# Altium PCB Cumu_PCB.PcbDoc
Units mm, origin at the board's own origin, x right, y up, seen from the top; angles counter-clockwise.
Board outline 80 x 100 mm, 2 copper layers (Top Layer, Bottom Layer); 158 components, 124 nets, 568 pads, 298 vias.
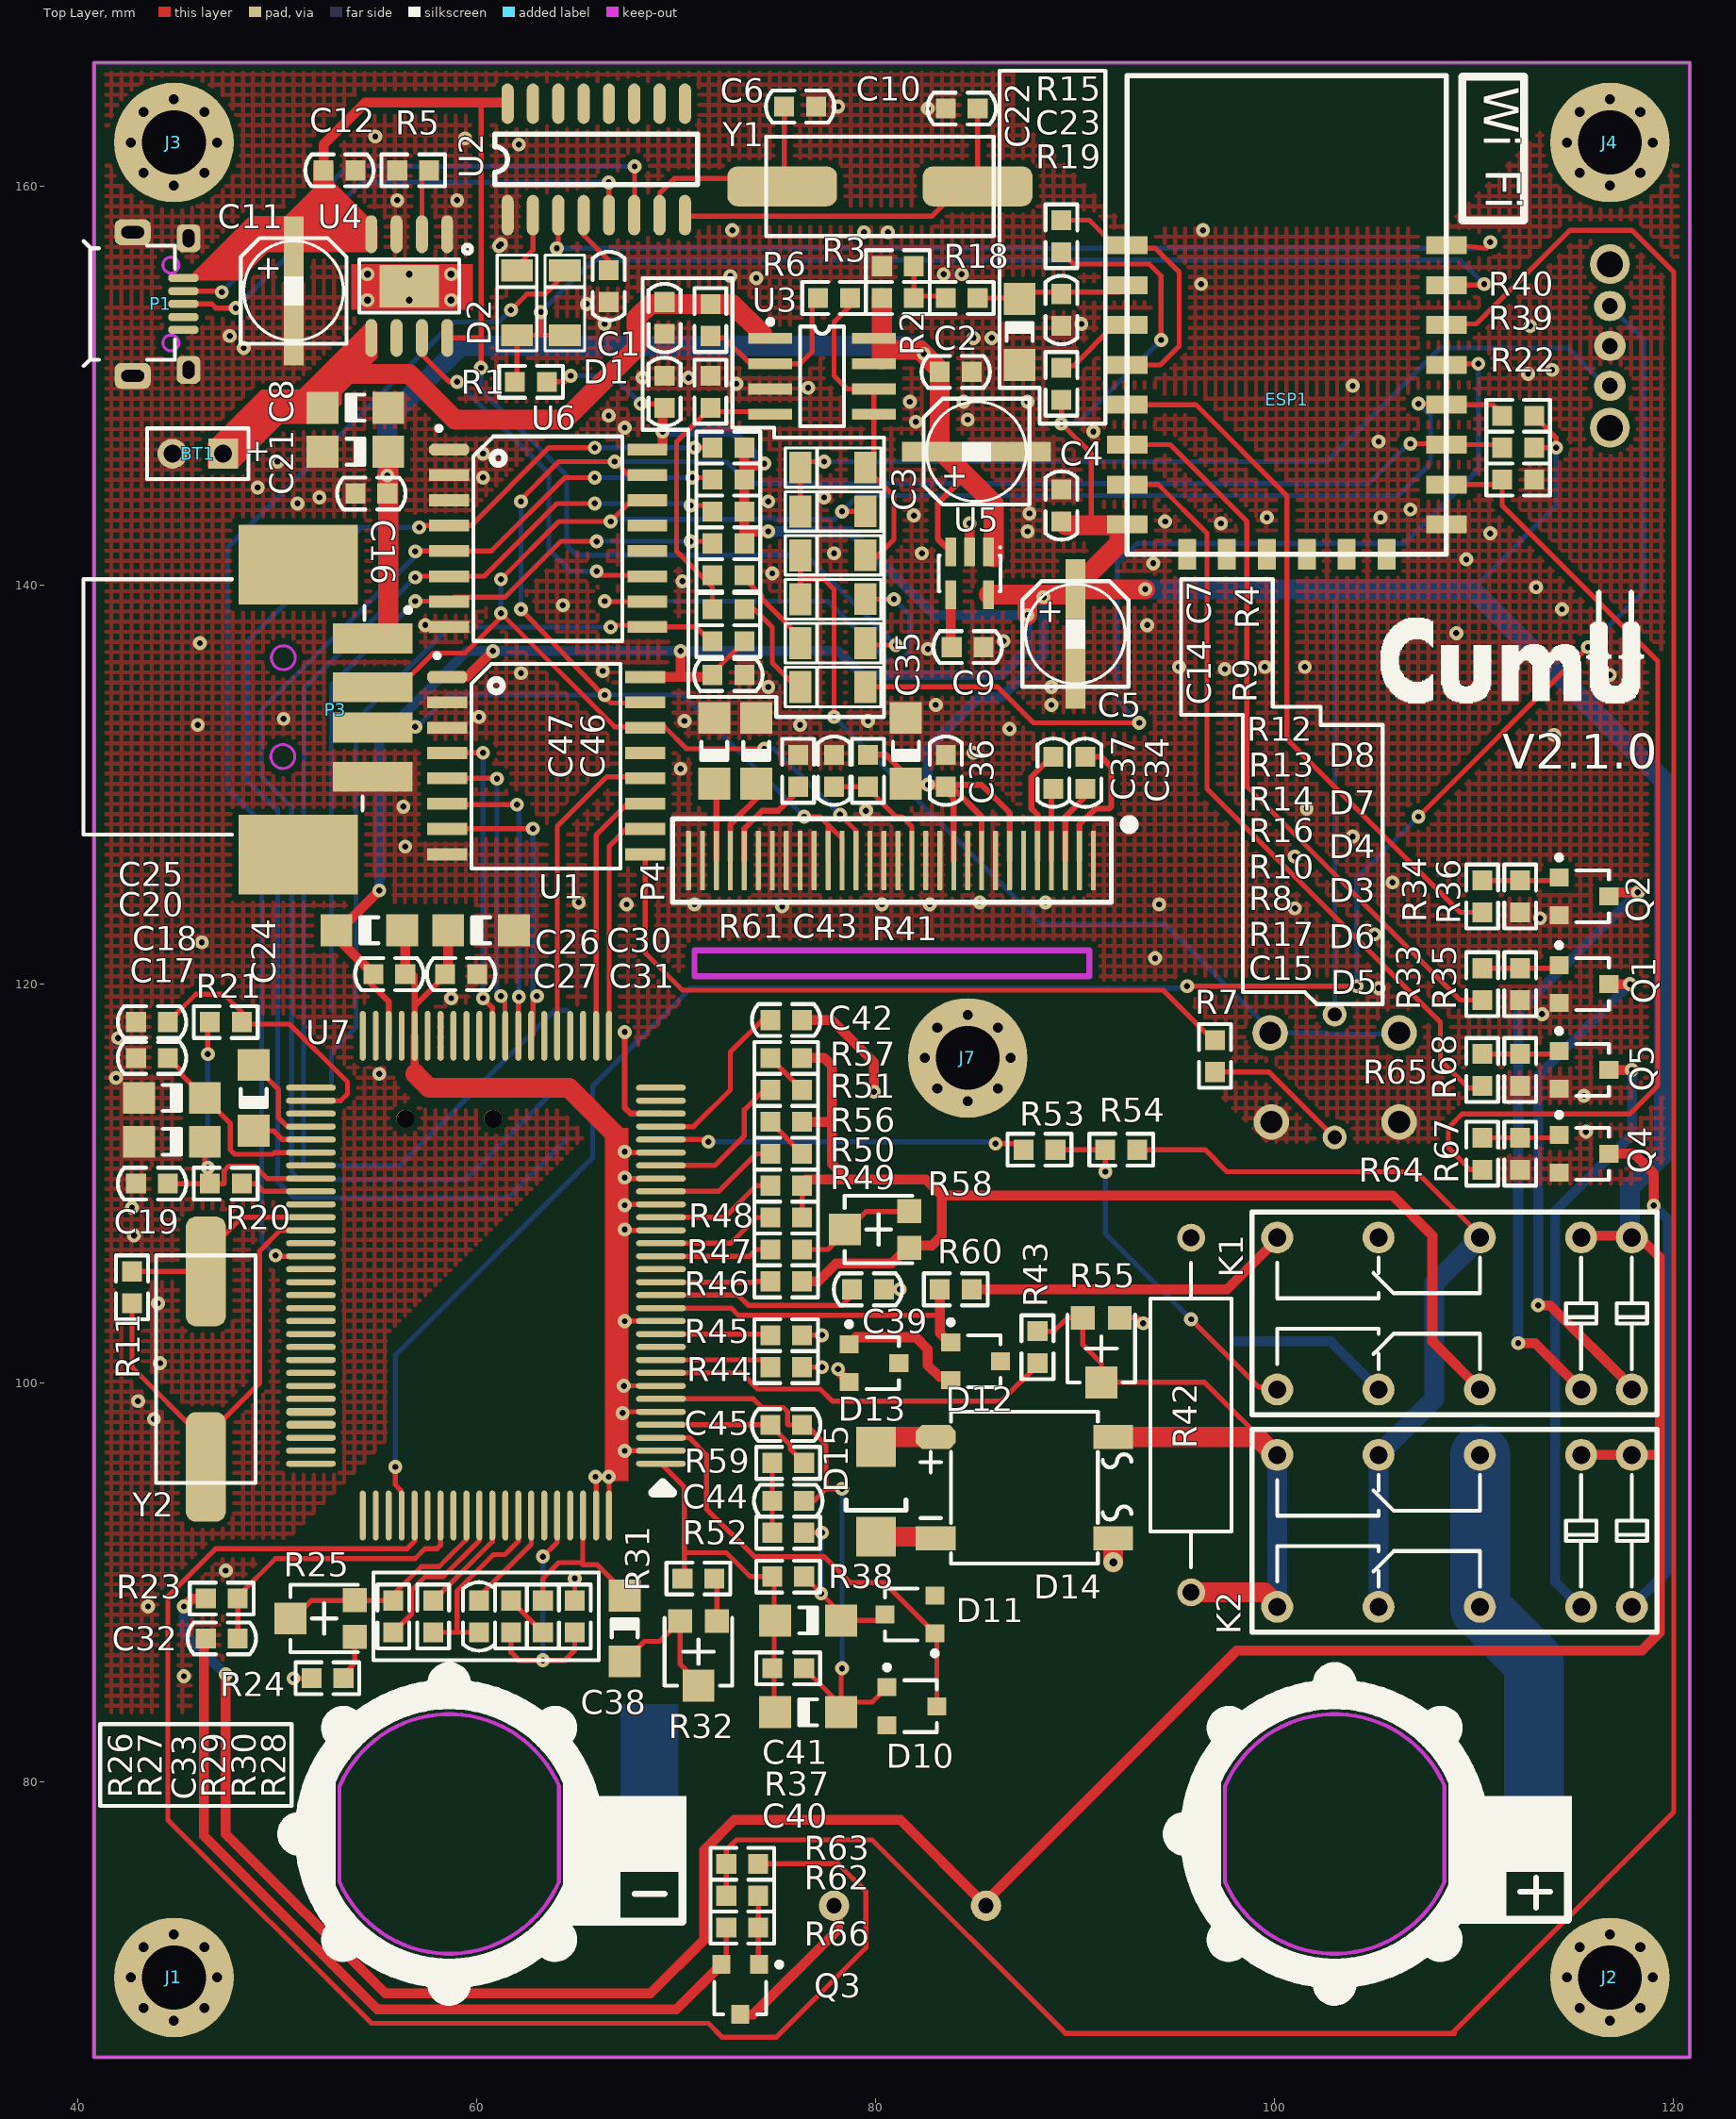
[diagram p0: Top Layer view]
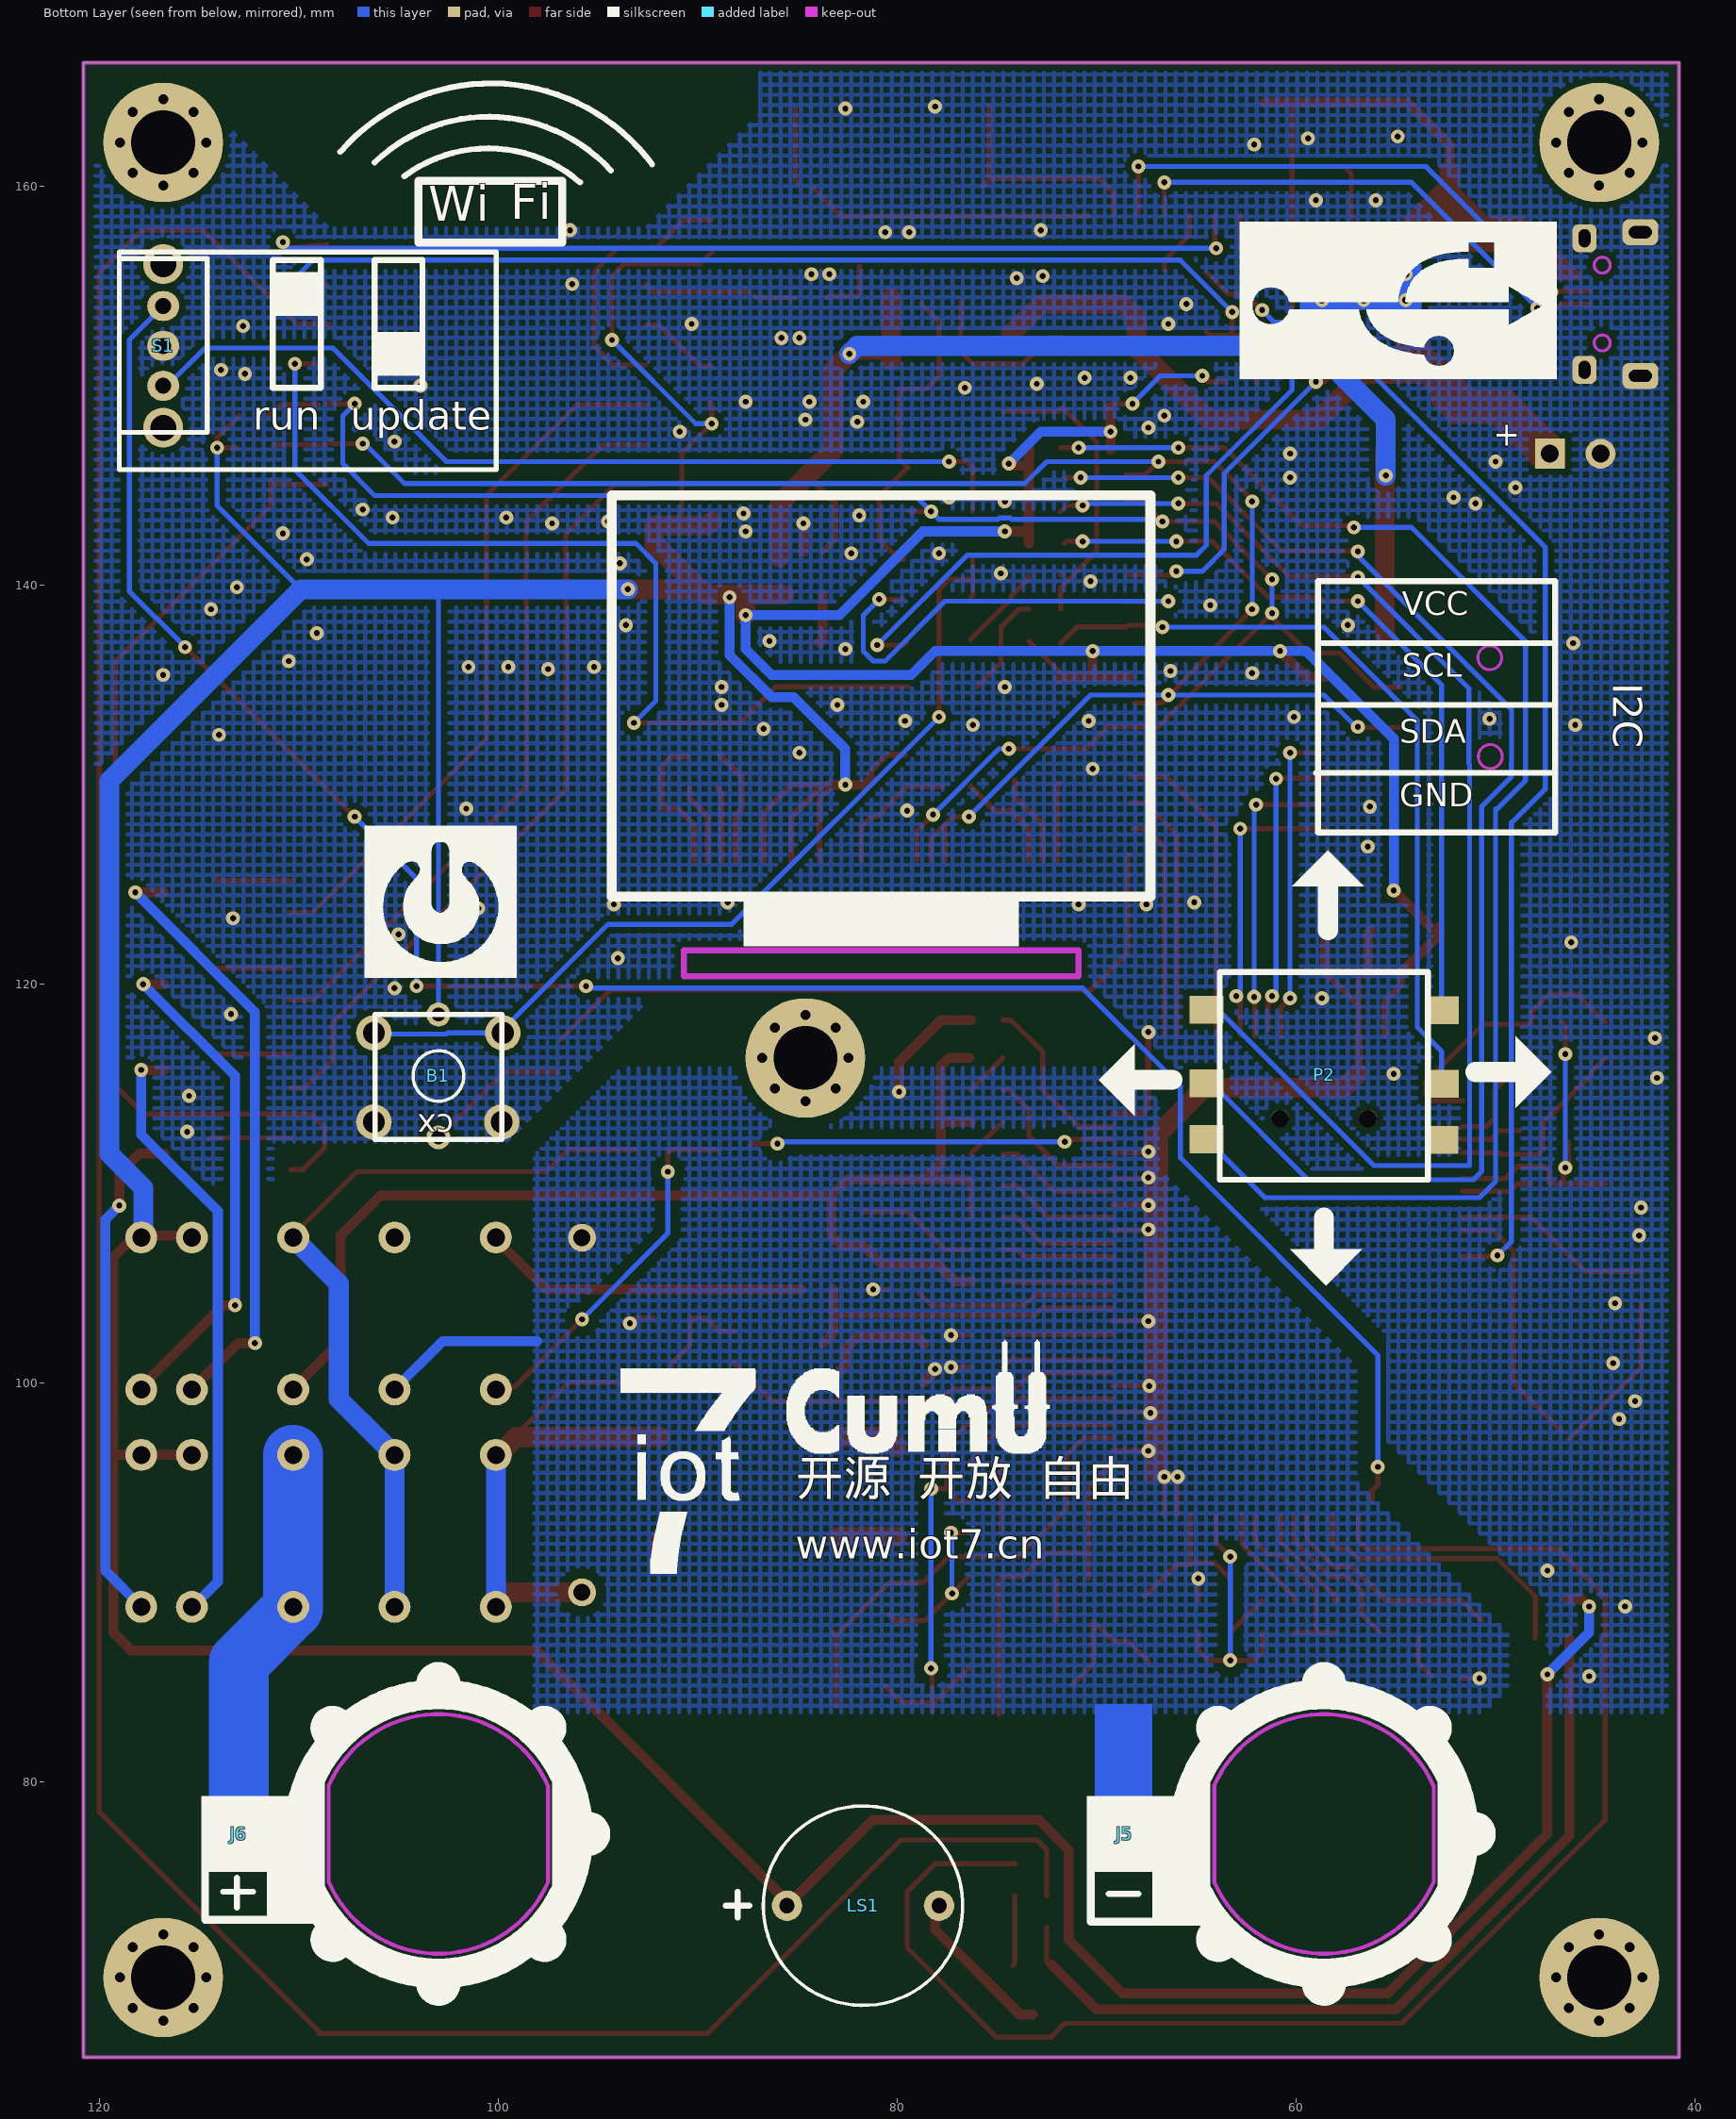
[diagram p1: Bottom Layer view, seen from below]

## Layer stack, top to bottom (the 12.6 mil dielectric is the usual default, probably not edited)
Top Layer: signal copper 0.0356
Dielectric: dielectric 0.32, FR-4, Dk 4.8
Bottom Layer: signal copper 0.0356

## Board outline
40.8,66.2 120.8,66.2 120.8,166.2 40.8,166.2

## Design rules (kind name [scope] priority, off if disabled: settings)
Clearance Clearance_3 [InNet('B-')] p1: gap=0.2
Clearance [All] p2: gap=0.2
ComponentClearance ComponentClearance_2 [InNet('B-')] p1: gap=0 collisioncheckmode=3 verticalgap=0 showdistances=FALSE
ComponentClearance ComponentClearance_1 [InNet('B+')] p2: gap=0 collisioncheckmode=3 verticalgap=0 showdistances=FALSE
ComponentClearance [All] p3: gap=0 collisioncheckmode=3 verticalgap=0 showdistances=FALSE
PlaneConnect [All] p1: planeconnectstyle=Direct reliefexpansion=0.508 reliefentries=4 reliefconductorwidth=0.254 reliefairgap=0.254
PolygonConnect [All] p1: connectstyle=Direct reliefconductorwidth=0.254 reliefentries=4 polygonreliefangle="90 Angle"
RoutingVias [All] p1: holewidth=0.3 width=0.5 viastyle="Through Hole" minholewidth=0.3 minwidth=0.5 maxholewidth=5 maxwidth=5
SilkscreenOverComponentPads [All] p1: minsilkscreentomaskgap=0.254
SolderMaskExpansion [All] p1: expansion=0.102
Width [All] p1: maxlimit=5 minlimit=0.2 preferedwidth=0.25
25 further rules are at their usual default settings.

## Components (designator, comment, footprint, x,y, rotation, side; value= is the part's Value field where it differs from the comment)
B1 "SW-led" SW-6-LED 103,115.4 r270 bottom locked
BT1 "3.7V" BAT-2 46,146.6 r180 top
C1 "Cap" 0603C 66.6,155 r270 top
C2 "Cap" 0603C 84,150.7 r180 top
C3 "Cap Pol2" SMD-EC-F5 82.8,146.7 r0 top
C4 "Cap" 0603C 89.3,144 r270 top
C5 "Cap Pol2" SMD-EC-F5 90,139.8 r270 top
C6 "Cap" 0603C 76.2,164 r0 top
C7 "Cap" 0603C 69.4,153.4 r90 top
C8 "Cap Pol2" CAP_A 53.9,148.9 r0 top
C9 "Cap" 0603C 84.6,136.9 r180 top
C10 "Cap" 0603C 84.3,163.9 r180 top
C11 "Cap Pol2" SMD-EC-F5 50.8,157 r270 top
C12 "Cap" 0603C 53.1,160.8 r180 top
C14 "Cap" 0603C 69.4,149.7 r90 top
C15 "Cap" 0603C 72.6,135.5 r0 top
C16 "Cap" 0603C 54.7,144.6 r0 top
C17 "Cap Pol2" CAP_A 44.7,112.1 r180 top
C18 "Cap Pol2" CAP_A 44.7,114.3 r180 top
C19 "Cap" 0603C 43.7,110 r0 top
C20 "Cap" 0603C 43.7,116.3 r0 top
C21 "Cap Pol2" CAP_A 53.9,146.7 r180 top
C22 "Cap Pol2" CAP_A 87.2,152.7 r270 top
C23 "Cap" 0603C 89.3,153.8 r90 top
C24 "Cap Pol2" CAP_A 48.8,114.3 r90 top
C25 "Cap" 0603C 43.7,118.1 r0 top
C26 "Cap Pol2" CAP_A 54.6,122.7 r0 top
C27 "Cap" 0603C 55.6,120.5 r180 top
C30 "Cap Pol2" CAP_A 60.2,122.7 r0 top
C31 "Cap" 0603C 59.2,120.5 r180 top
C32 "Cap" 0603C 47.2,87.2 r0 top
C33 "Cap" 0603C 60.1,88.3 r270 top
C34 "Cap" 0603C 90.5,130.6 r90 top
C35 "Cap Pol2" CAP_A 81.5,131.7 r90 top
C36 "Cap" 0603C 83.5,130.7 r90 top
C37 "Cap" 0603C 88.9,130.6 r270 top
C38 "Cap Pol2" CAP_A 67.4,87.7 r270 top
C39 "Cap" 0603C 79.6,104.7 r0 top
C40 "Cap Pol2" CAP_A 76.6,83.5 r0 top
C41 "Cap Pol2" CAP_A 76.6,88.1 r180 top
C42 "Cap" 0603C 75.5,118.2 r0 top
C43 "Cap" 0603C 77.9,130.7 r270 top
C44 "Cap" 0603C 75.6,94.1 r0 top
C45 "Cap" 0603C 75.5,97.9 r0 top
C46 "Cap Pol2" CAP_A 74,131.7 r90 top
C47 "Cap Pol2" CAP_A 71.9,131.7 r90 top
D1 "MBRA340" "M7 1206" 64.4,153.4 r90 top
D2 "MBRA340" "M7 1206" 62,153.4 r90 top
D3 "MBRA340" "M7 1206" 78.6,139.3 r180 top
D4 "MBRA340" "M7 1206" 78.6,141.5 r180 top
D5 "MBRA340" "M7 1206" 78.6,134.9 r180 top
D6 "MBRA340" "M7 1206" 78.6,137.1 r180 top
D7 "MBRA340" "M7 1206" 78.6,143.7 r180 top
D8 "MBRA340" "M7 1206" 78.6,145.9 r180 top
D10 "MMBD914" SOT-23B 81.8,83.8 r270 top
D11 "MMBD914" SOT-23B 81.7,88.4 r90 top
D12 "BAV199" SOT-23B 85,101.1 r270 top
D13 "BAV199" SOT-23B 79.9,101 r270 top
D14 "Bridge1" DB107S 83,97.3 r0 top
D15 "MBRA340" SMA 80,96.8 r270 top
ESP1 "ESP_12E/ESP-12F" ESP12_BOT 100.6,149.3 r0 top
J1 "Socket" GDK 44.8,70.2 r0 top
J2 "Socket" GDK 116.8,70.2 r0 top
J3 "Socket" GDK 44.8,162.2 r0 top
J4 "Socket" GDK 116.8,162.2 r0 top
J5 "B-" pen 58.6,77.4 r0 bottom locked
J6 "B+" PEN 103,77.4 r0 bottom locked
J7 "Socket" GDK 84.6,116.3 r0 top
K1 "磁保持继电器" HFD2/005-M-L2 117.9,107.3 r180 top
K2 "磁保持继电器" HFD2/005-M-L2 117.9,96.4 r180 top
LS1 "Bell" BUZZ 77.9,73.8 r0 bottom
P1 "MicroUSB" "USB_MICRO -72/66" 45,154.1 r180 top
P2 "Header 6" 5xiang-10*10 52.7,112.2 r270 bottom locked
P3 "Header 4" USB_tie 44.2,133.7 r180 top
P4 "Header 30" 0,96OLED 90.9,126.2 r180 top locked
Q1 "QNPN" SOT-23B 115.5,120 r270 top
Q2 "QNPN" SOT-23B 115.5,124.4 r270 top
Q3 "QNPN" SOT-23B 73.2,69.6 r180 top
Q4 "QNPN" SOT-23B 115.5,111.5 r270 top
Q5 "QNPN" SOT-23B 115.5,115.7 r270 top
R1 "Res2" 0603R 62.7,150.2 r0 top
R2 "Res2" 0603R 81.1,154.4 r180 top
R3 "Res2" 0603R 81.1,156 r0 top
R4 "Res2" 0603R 71.7,153.3 r270 top
R5 "Res2" 0603R 56.8,160.8 r0 top
R6 "Res2" 0603R 77.9,154.4 r180 top
R7 "Res2" 0603R 97,116.4 r90 top
R8 "Res2" 0603R 72.6,138.8 r180 top
R9 "Res2" 0603R 71.7,149.7 r270 top
R10 "Res2" 0603R 72.6,140.5 r180 top
R11 "Res2" 0603R 42.7,104.8 r270 top
R12 "Res2" 0603R 72.6,146.9 r0 top
R13 "Res2" 0603R 72.6,145.3 r180 top
R14 "Res2" 0603R 72.6,143.7 r0 top
R15 "Res2" 0603R 89.3,157.5 r270 top
R16 "Res2" 0603R 72.6,142.1 r0 top
R17 "Res2" 0603R 72.6,137.2 r0 top
R18 "Res2" 0603R 84.3,154.4 r0 top
R19 "Res2" 0603R 89.3,150.1 r90 top
R20 "Res2" 0603R 47.4,110 r0 top
R21 "Res2" 0603R 47.4,118.1 r0 top
R22 "Res2" 0603R 112.2,145.3 r180 top
R23 "Res2" 0603R 47.2,89.2 r180 top
R24 "Res2" 0603R 52.5,85.2 r180 top
R25 "RPot" R3*3 53.1,88.2 r90 top
R26 "Res2" 0603R 55.8,88.3 r90 top
R27 "Res2" 0603R 57.8,88.3 r270 top
R28 "Res2" 0603R 64.9,88.3 r90 top
R29 "Res2" 0603R 61.7,88.3 r270 top
R30 "Res2" 0603R 63.3,88.3 r270 top
R31 "Res2" 0603R 71.1,90.2 r180 top
R32 "RPot" R3*3 71.1,87.3 r180 top
R33 "Res2" 0603R 110.4,120 r270 top
R34 "Res2" 0603R 110.4,124.4 r270 top
R35 "Res2" 0603R 112.3,120 r90 top
R36 "Res2" 0603R 112.3,124.4 r90 top
R37 "Res2" 0603R 75.6,85.7 r0 top
R38 "Res2" 0603R 75.6,90.3 r0 top
R39 "Res2" 0603R 112.2,146.9 r0 top
R40 "Res2" 0603R 112.2,148.5 r0 top
R41 "Res2" 0603R 79.6,130.7 r270 top
R42 "2W 1%" AXIAL-0.7 95.8,98.4 r90 top
R43 "Res2" 0603R 88.1,101.8 r90 top
R44 "Res2" 0603R 75.5,100.8 r0 top
R45 "Res2" 0603R 75.5,102.4 r0 top
R46 "Res2" 0603R 75.5,105.1 r0 top
R47 "Res2" 0603R 75.5,106.7 r0 top
R48 "Res2" 0603R 75.5,108.3 r0 top
R49 "Res2" 0603R 75.5,109.9 r0 top
R50 "Res2" 0603R 75.5,111.5 r0 top
R51 "Res2" 0603R 75.5,114.7 r0 top
R52 "Res2" 0603R 75.6,92.5 r180 top
R53 "Res2" 0603R 88.2,111.7 r0 top
R54 "" 0603R 92.3,111.7 r0 top
R55 "RPot" R3*3 91.3,102.5 r180 top
R56 "Res2" 0603R 75.5,113.1 r0 top
R57 "Res2" 0603R 75.5,116.3 r0 top
R58 "RPot" R3*3 80.9,107.7 r90 top
R59 "Res2" 0603R 75.6,96 r0 top
R60 "Res2" 0603R 84,104.7 r0 top
R61 "Res2" 0603R 76.1,130.7 r90 top
R62 "Res2" 0603R 73.3,74.3 r180 top
R63 "Res2" 0603R 73.3,75.9 r0 top
R64 "Res2" 0603R 110.4,111.5 r270 top
R65 "Res2" 0603R 110.4,115.7 r270 top
R66 "Res2" 0603R 73.3,72.7 r0 top
R67 "Res2" 0603R 112.3,111.5 r90 top
R68 "Res2" 0603R 112.3,115.7 r90 top
S1 "SW-SPDT" SS-12D07 116.8,150 r90 bottom
U1 "PCF8574" SOP-16 58.5,135.4 r0 top
U2 "CH340G" SO-16 65.9,158.2 r90 top
U3 "AO4606" SO-8 77.3,150.3 r270 top
U4 "TP4056" "SO-8 - 9" 56.6,155 r270 top
U5 "CAT6219" MA05B 84.7,140.6 r180 top
U6 "PCF8574" SOP-16 58.6,146.8 r0 top
U7 "FS9721" QFP100 69,95.9 r90 top
Y1 "12M" HC-49 80.2,160 r180 top
Y2 "4M" HC-49 46.4,100.7 r90 top

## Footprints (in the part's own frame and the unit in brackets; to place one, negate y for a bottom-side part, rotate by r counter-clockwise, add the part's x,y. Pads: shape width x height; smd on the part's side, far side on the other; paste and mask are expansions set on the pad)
0,96OLED [mm]
  rrect50% 0.25x3 smd: 1(0,0) 2(0.7,0) 3(1.4,0) 4(2.1,0) 5(2.8,0) 6(3.5,0) 7(4.2,0) 8(4.9,0) 9(5.6,0) 10(6.3,0) 11(7,0) 12(7.7,0) 13(8.4,0) 14(9.1,0) 15(9.8,0) 16(10.5,0) 17(11.2,0) 18(11.9,0) 19(12.6,0) 20(13.3,0) 21(14,0) 22(14.7,0) 23(15.4,0) 24(16.1,0) 25(16.8,0) 26(17.5,0) 27(18.2,0) 28(18.9,0) 29(19.6,0) 30(20.3,0)
  silkscreen extent -2,-2.1 21.1,2.1
5xiang-10*10 [mm]
  round 0.9 hole 0.9: 0(-1.056,-8.1) 0(-1.056,-3.7)
  rect 1.4x1.7 smd: 1(-0.001,-0.003) 2(-2.8,0) 3(-6.5,0) 4(-0.026,-11.789) 5(-2.825,-11.786) 6(-6.525,-11.786)
  silkscreen extent -8.41,-11.13 2.01,-0.69
0603C [mm] "贴片带丝印"
  rect 1x1 smd: 1(-0.8,0) 2(0.8,0)
  silkscreen extent -1.72,-0.8 1.72,0.8, body extent -1.14,-0.48 1.14,0.48, height 0.4
0603R [mm] "贴片带丝印"
  rect 1x1 smd: 1(-0.8,0) 2(0.8,0)
  silkscreen extent -1.6,-0.8 1.6,0.8, body extent -1.14,-0.48 1.14,0.48, height 0.4
AXIAL-0.7 [mm] "Axial Device, Thru-Hole; 2 Leads; 0.7 in Pin Spacing"
  round 1.4 hole 0.85: 1(-8.89,0) 2(8.89,0)
  silkscreen extent -7.62,-2.03 7.62,2.03
BAT-2 [mm] "Multicell Battery; 2 Leads"
  rect 1.5x1.5 hole 0.9: 1(-1.27,0)
  round 1.5 hole 0.9: 2(1.27,0)
  silkscreen extent -2.54,-1.27 2.54,1.27
BUZZ [mil]
  round 60 hole 30: 1(0,0) 2(300,0)
  silkscreen extent -47,-197 347,197
CAP_A [mm] "Chip Capacitor, Body 3.81x1.27mm, IPC Medium Density"
  rect 1.6x1.6 smd: 1(-1.65,0) 2(1.65,0)
  silkscreen extent -0.45,-0.65 0.45,0.65, body extent -2.1,-0.82 2.1,0.82, height 1.66
DB107S [mm] "整流桥"
  oct 2x1.2 smd: 1(0,0)
  rect 2x1.2 smd: 2(8.89,0) 3(0,-5.08) 4(8.89,-5.08)
  silkscreen extent -0.76,-6.35 9.8,1.27
ESP12_BOT [mm]
  rect 2.032x0.9 smd: 1(-8,7.75) 2(-8,5.75) 3(-8,3.75) 4(-8,1.75) 5(-8,-0.25) 6(-8,-2.25) 7(-8,-4.25) 8(-8,-6.25) 15(8,-6.25) 16(8,-4.25) 17(8,-2.25) 18(8,-0.25) 19(8,1.75) 20(8,3.75) 21(8,5.75) 22(8,7.75)
  rect 0.9x1.524 smd: 9(-5,-7.75) 10(-3,-7.75) 11(-1,-7.75) 12(1,-7.75) 13(3,-7.75) 14(5,-7.75)
  silkscreen extent -8,-7.75 8,16.25
GDK [mm] "固定孔"
  round 6 hole 3.2: 1(0,0)
HC-49 [mm]
  rrect50% 5.5x2 smd: 1(-4.9,0) 2(4.9,0)
  silkscreen extent -5.7,-2.49 5.7,2.49
HFD2/005-M-L2 [mm] "磁保持继电器"
  round 1.6 hole 0.9: 1(0,0) 2(2.54,0) 4(7.62,0) 6(12.7,0) 8(17.78,0) 9(17.78,7.62) 11(12.7,7.62) 13(7.62,7.62) 15(2.54,7.62) 16(0,7.62)
  silkscreen extent -1.27,-1.27 19.05,8.89
"M7 1206" [mm]
  rect 1.1x1.6 smd: 1(-0.869,-0.005) 2(2.388,0)
  silkscreen extent -1.65,-0.99 3.15,0.99
MA05B [mm] "SOT-23/SC-74A; 5 Leads; Body 3 x 3 mm, inc. leads (LxW max)"
  rect 0.55x1.45 smd: 1(-0.95,-1.075) 2(0,-1.075) 3(0.95,-1.075) 4(0.95,1.075) 5(-0.95,1.075)
  silkscreen extent -1.58,-1.35 1.55,0.9
pen [mm] "表笔孔"
  round 3 hole 1.2: 1(10,0)
  Keep-Out Layer lines w0.2: -5.5,-2.4 -5.5,2.4 cw(c0.002,0.009) 5.504,2.402 ; -5.499,-2.382 ccw(c0.009,-0.002) 5.504,-2.41 ; 5.5,2.4 5.5,-2.4
  silkscreen extent -8.11,-8.12 11.9,8.12
PEN [mm] "表笔孔"
  round 3 hole 1.2: 1(10,0)
  Keep-Out Layer lines w0.2: -5.5,2.4 cw(c0.002,0.009) 5.504,2.402 ; -5.5,2.4 -5.5,-2.4 ; -5.499,-2.382 ccw(c0.009,-0.002) 5.504,-2.41 ; 5.5,2.4 5.5,-2.4
  silkscreen extent -8.11,-8.12 11.9,8.12
QFP100 [mm]
  oval 0.3x2.5 smd: 1(0.06,-0.218) 2(0.71,-0.218) 3(1.36,-0.218) 4(2.01,-0.218) 5(2.66,-0.218) 6(3.31,-0.218) 7(3.96,-0.218) 8(4.61,-0.218) 9(5.26,-0.218) 10(5.91,-0.218) 11(6.56,-0.218) 12(7.21,-0.218) 13(7.86,-0.218) 14(8.51,-0.218) 15(9.16,-0.218) 16(9.81,-0.218) 17(10.46,-0.218) 18(11.11,-0.218) 19(11.76,-0.218) 20(12.41,-0.218) 21(13.06,-0.218) 22(13.71,-0.218) 23(14.36,-0.218) 24(15.01,-0.218) 25(15.66,-0.218) 26(16.31,-0.218) 27(16.96,-0.218) 28(17.61,-0.218) 29(18.26,-0.218) 30(18.91,-0.218) 51(18.91,17.332) 52(18.26,17.332) 53(17.61,17.332) 54(16.96,17.332) 55(16.31,17.332) 56(15.66,17.332) 57(15.01,17.332) 58(14.36,17.332) 59(13.71,17.332) 60(13.06,17.332) 61(12.41,17.332) 62(11.76,17.332) 63(11.11,17.332) 64(10.46,17.332) 65(9.81,17.332) 66(9.16,17.332) 67(8.51,17.332) 68(7.86,17.332) 69(7.21,17.332) 70(6.56,17.332) 71(5.91,17.332) 72(5.26,17.332) 73(4.61,17.332) 74(3.96,17.332) 75(3.31,17.332) 78(1.36,17.332) 79(0.71,17.332) 80(0.06,17.332)
  oval 2.5x0.3 smd: 31(21.51,2.382) 32(21.51,3.032) 33(21.51,3.682) 34(21.51,4.332) 35(21.51,4.982) 36(21.51,5.632) 37(21.51,6.282) 38(21.51,6.932) 39(21.51,7.582) 40(21.51,8.232) 41(21.51,8.882) 42(21.51,9.532) 43(21.51,10.182) 44(21.51,10.832) 45(21.51,11.482) 46(21.51,12.132) 47(21.51,12.782) 48(21.51,13.432) 49(21.51,14.082) 50(21.51,14.732) 81(-2.54,14.732) 82(-2.54,14.082) 83(-2.54,13.432) 84(-2.54,12.782) 85(-2.54,12.132) 86(-2.54,11.482) 87(-2.54,10.832) 88(-2.54,10.182) 89(-2.54,9.532) 90(-2.54,8.882) 91(-2.54,8.232) 92(-2.54,7.582) 93(-2.54,6.932) 94(-2.54,6.282) 95(-2.54,5.632) 96(-2.54,4.982) 97(-2.54,4.332) 98(-2.54,3.682) 99(-2.54,3.032) 100(-2.54,2.382)
  oval 0.4x2.5 smd: 76(2.66,17.332) 77(2.01,17.332)
  silkscreen extent -1.39,-0.77 -0.92,0.15
R3*3 [mm] "Surface Mount Quartz Crystal; Body 3.4 x 2.7 mm (LxW max)"
  rect 1.2x1.2 smd: 1(-0.924,-0.77) 2(0.924,-0.77)
  rect 1.6x1.6 smd: 3(0,2.464)
  silkscreen extent -1.69,-0.92 1.69,2.46
SMA [mm]
  rect 2x2 smd: 1(0,0) 2(4.5,0)
  silkscreen extent 2.67,-1.5 3.18,1.5
SMD-EC-F5 [mm]
  rect 3x1 smd: 1(0,0) 2(4.477,0)
  silkscreen extent -0.41,-2.65 4.89,2.66
SO-8 [mm]
  rect 0.55x2.2 smd: 1(-2.078,-2.6) 2(-0.808,-2.6) 3(0.462,-2.6) 4(1.732,-2.6) 5(1.732,2.6) 6(0.462,2.6) 7(-0.808,2.6) 8(-2.078,2.6)
  silkscreen extent -3.03,-2.72 2.33,1.1
"SO-8 - 9" [mm] "SOP, 8-Leads, Body 5.0x4.0mm (max), Pitch 1.27mm, IPC Medium Density"
  rect 2.13x3 smd: 0(0,0)
  oval 1.9x0.6 smd: 1(-2.6,1.905) 2(-2.6,0.635) 3(-2.6,-0.635) 4(-2.6,-1.905) 5(2.6,-1.905) 6(2.6,-0.635) 7(2.6,0.635) 8(2.6,1.905)
  silkscreen extent -2.05,-2.5 1.33,3.12
SO-16 [mil]
  oval 80x24 smd: 1(14,172) 2(14,122) 3(14,72) 4(14,22) 5(14,-28) 6(14,-78) 7(14,-128) 8(14,-178) 9(234,-178) 10(234,-128) 11(234,-78) 12(234,-28) 13(234,22) 14(234,72) 15(234,122) 16(234,172)
  silkscreen extent 74,-203 174,197
SOP-16 [mm]
  oct 2x0.6 smd: 1(0,0)
  rect 2x0.6 smd: 2(0,-1.27) 3(0,-2.54) 4(0,-3.81) 5(0,-5.08) 6(0,-6.35) 7(0,-7.62) 8(0,-8.89) 9(9.933,-8.89) 10(9.933,-7.62) 11(9.933,-6.35) 12(9.933,-5.08) 13(9.933,-3.81) 14(9.933,-2.54) 15(9.933,-1.27) 16(9.933,0)
  silkscreen extent -0.59,-9.6 8.69,1.15
SOT-23B [mm] "SOT-23; 3 Leads; Body 3.0 x 2.6 mm, inc. leads (LxW max)"
  rect 0.9x0.95 smd: 1(-0.95,-1.25) 2(0.95,-1.25) 3(0,1.25)
  silkscreen extent -2.07,-1.37 1.3,1.25
SS-12D07 [mm] "拨动开关"
  round 2 hole 1.3: 0(-2.1,0) 0(6.1,0)
  oval 1.5x1.6 hole 0.8: 1(0,0) 2(2,0) 3(4,0)
  silkscreen extent -2.34,-2.2 6.38,2.2
SW-6-LED [mm]
  round 1.778 hole 1.1: 1(-2.156,3.234) 2(-2.156,-3.234) 3(2.31,3.175) 4(2.31,-3.234)
  round 1.2 hole 0.7: 5(-3.08,0) 6(3.08,0)
  silkscreen extent -3.08,-3.17 3.18,3.18
"USB_MICRO -72/66" [mm] "USB牛角"
  oct 1.5x0.4 smd: 1(-0.279,-1.3) 2(-0.279,-0.65) 3(-0.279,0) 4(-0.279,0.65) 5(-0.279,1.295)
  rrect50% 1.2x1.4 hole 0.6 slot 0.9 at 90 deg: 5(-0.535,3.3) 5(-0.535,-3.3)
  rrect50% 1.8x1.3 hole 0.6 slot 1.15 at 0 deg: 5(2.265,3.6) 5(2.265,-3.6)
  Keep-Out Layer circle w0.15: c0.35,-1.95 r0.4
  Keep-Out Layer circle w0.15: c0.35,1.95 r0.4
  silkscreen extent 0.15,-3.15 4.72,3.1
USB_tie [mm] "Connector; USB2.0, Type B, SM; 5 Position; Right Angle"
  rect 4x1.5 smd: 1(-10.566,-3.632) 2(-10.566,-1.194) 3(-10.566,0.838) 4(-10.566,3.302)
  rect 6x4 smd: 5(-6.833,7.214) 6(-6.833,-7.341)
  Keep-Out Layer circle w0.15: c-6.086,-2.667 r0.6
  Keep-Out Layer circle w0.15: c-6.061,2.286 r0.6
  silkscreen extent -12.47,-6.6 3.94,6.2

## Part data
BT1: library part Battery, "Multicell Battery"
C1 C2 C4 C6 C7 C9 C10 C12 C14 C15 C16 C19 C20 C23 C25 C27 C31 C32 C33 C34 C36 C37 C39 C42 C43 C44 C45: "Capacitor"
C3 C5 C8 C11 C17 C18 C21 C22 C24 C26 C30 C35 C38 C40 C41 C46 C47: "Polarized Capacitor (Axial)"
D1 D2 D3 D4 D5 D6 D7 D8 D10 D11 D15: library part "Diode 1N5408", "3 Amp Medium Power Silicon Rectifier Diode"
D14: "Full Wave Diode Bridge"
ESP1: library part ESP_12
J5 J6: library part Socket, "Socket"
K1 K2: library part HFD2/005-M-L2
LS1: "Electrical Bell"
P1: library part "Header 5", "Header, 5-Pin"
P2: "Header, 6-Pin"
P3: "Header, 4-Pin"
P4: "Header, 30-Pin"
Q1 Q2 Q3 Q4 Q5: "NPN Bipolar Transistor"
R1 R2 R3 R4 R5 R6 R7 R8 R9 R10 R11 R12 R13 R14 R15 R16 R17 R18 R19 R20 R21 R22 R23 R24 R26 R27 R28 R29 R30 R31 R33 R34 R35 R36 R37 R38 R39 R40 R41 R43 R44 R45 R46 R47 R48 R49 R50 R51 R52 R53 R56 R57 R59 R60 R61 R62 R63 R64 R65 R66 R67 R68: "Resistor"
R25 R32 R55 R58: "Potentiometer"
R42 R54: library part Res2, "Resistor"
S1: "SPDT Subminiature Toggle Switch, Right Angle Mounting, Vertical Actuation"
U3: "Dual P-Channel 2.5V (G-S) Rated  MOSFET"
U5: library part PM3101
U7: library part Component_1
Y1 Y2: library part XTAL, "Crystal Oscillator"

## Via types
v1: diameter 0.7, hole 0.3, Top Layer to Bottom Layer, 251 vias
v2: diameter 1, hole 0.5, Top Layer to Bottom Layer, 40 vias
v3: diameter 0.7, hole 0.35, Top Layer to Bottom Layer, 6 vias
v4: diameter 1, hole 0.4, Top Layer to Bottom Layer, 1 vias

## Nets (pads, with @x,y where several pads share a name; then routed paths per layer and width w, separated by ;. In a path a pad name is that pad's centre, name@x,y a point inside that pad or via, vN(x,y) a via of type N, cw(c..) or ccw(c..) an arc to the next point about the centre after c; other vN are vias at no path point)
5V: C11.1 C12.2 D6.1 P1.1 U2.16 U4.4 U4.8 | length 57.3
  Top Layer w0.25: U4.8 60.2,152.4 ; v1@60.2,151 60.2,152.4 ; 60.2,164.2 60.2,152.4 ; D6.1@79.5,137.2 79.7,137 v1(81,137)
  Top Layer w0.5: C12.2 52.3,162.1 54.4,164.2 60.2,164.2 U2.16@61.6,164.2
  Bottom Layer w0.25: v1@60.2,151 60.2,149.8 64.5,145.5 64.5,142 65,141.5 76.5,141.5 v1(81,137)
  other v1: 60.2,150.9
ADC: R2.1 R3.2 R18.1 | length 3.1
  Top Layer w0.25: R3.2 81.9,154.6 82,154.5 83.4,154.5 R18.1
ADP2: U7.95
B+: J6.1 K2.4 K2.13 | length 20.2
  Bottom Layer w1: K2.4 110.28,96.48 K2.4@110.3,96.5
  Bottom Layer w3: K2.4@110.3,96.4 110.3,88.7 113,86 J6.1
B-: C26.2 C27.1 C30.1 C31.2 C39.2 C42.2 D13.2 D14.4 J5.1 K1.11 R24.2 R28.2 R42.2 R44.2 R45.2 R55.1 U7.2 U7.5 U7.7 U7.12 U7.19 U7.21 U7.23 U7.25 U7.46 U7.99 U7.100 | length 64.3
  Top Layer w0.25: v1(50.8,85.2) R24.2 ; R28.2 v1(64.9,90.2) ; v1(65.936,95.3) 65.968,95.268 U7.99 ; v1(66.6,95.3) 66.618,95.282 U7.100 ; v1(67.3,98.5) 67.36,98.56 U7.5 ; v1(67.36,99.86) U7.7 ; v1(67.4,96.6) 67.41,96.61 U7.2 ; v1(67.4,103.1) 67.41,103.11 U7.12 ; v1(67.4,107.7) 67.44,107.66 U7.19 ; v1(67.4,108.92) 67.44,108.96 U7.21 ; v1(67.4,110.3) 67.44,110.26 U7.23 ; v1(67.4,111.6) 67.44,111.56 U7.25 ; R44.2 v1(77.3,100.8) ; R45.2 v1(77.3,102.4) ; v1@78,100.7 v1(78.1,100.7) ; C39.2 v1(81.2,104.7) ; R55.1 93.13,103.27 v1(93.4,103)
  Top Layer w0.3: C27.1@56.7,120.6 56.868,120.432 56.868,118.9 ; U7.46 56.868,118.9 ; C31.2@58.5,120.4 58.368,120.4 56.868,118.9
  Top Layer w0.4: 56.868,115.532 U7.46
  Top Layer w0.5: C26.2 56.4,122.55 C27.1 ; 56.868,115.532 56.9,115.5 ; C31.2@58.4,120.7 58.55,120.85 C30.1 ; C42.2 77.8,118.2 79.9,116.1 v1(79.9,114.6) ; v1@78,100.7 D13.2
  Top Layer w1: 56.9,115.5 57.6,114.8 64.6,114.8 67,112.4 ; D14.4 91.89,91.01 v4(91.9,91.02)
  Bottom Layer w0.5: 98.044,102.1 102.8,102.1 102.9,102 ; 102.88,102 K1.11
BAT_C: U4.7 U6.11 | length 18.9
  Top Layer w0.25: U4.7 57.235,151.565 58.6,150.2 58.8,150.2 v1@58.9,150.3 ; v1(66,140.7) 66.2,140.5 U6.11@68.4,140.5
  Bottom Layer w0.25: v1@58.9,150.3 63.6,145.6 63.6,141.8 64.7,140.7 v1(66,140.7)
  other v1: 59,150.2
ENTX: S1.3 U7.84 | length 106.2
  Top Layer w0.25: v1(55.9,95.8) 55.9,94.9 56.2,94.6 U7.84@56.2,94.1 ; v1(95.6,119.9) v1(104.1,119.9) ; v1(107.2,128.4) v1(115.7,136.9)
  Bottom Layer w0.25: v1(55.9,95.8) 55.9,101.4 65.8,111.3 65.8,114.9 70.7,119.8 95.5,119.8 v1(95.6,119.9) ; v1(104.1,119.9) 104.1,125.3 v1(107.2,128.4) ; v1(115.7,136.9) 118.5,139.7 118.5,152.3 S1.3
ESP_BEEP: ESP1.20 R62.2 R63.1 | length 150.2
  Top Layer w0.25: R62.2 R63.1 72.5,76.6 73,77.1 79.8,77.1 89.5,67.4 108.9,67.4 ; ESP1.20@108.5,153.1 110.1,153.1 114.8,157.8 117.9,157.8 120,155.7 120,78.5 108.9,67.4 ; 109,67.4 108.9,67.4
ESP_RST: ESP1.1 ESP1.4 R15.1 | length 13.7
  Top Layer w0.25: R15.1 90.7,158.3 92.1,156.9 94,156.9 95.2,155.7 95.2,152 94.25,151.05 ESP1.4
FS_BEEP: R63.2 U7.85 | length 76.2
  Top Layer w0.25: U7.85 56.868,92.068 56.5,91.7 46.9,91.7 44.5,89.3 44.5,78.1 54.7,67.9 71.6,67.9 72.3,67.2 75,67.2 79.5,71.7 79.5,74.5 78.1,75.9 R63.2
FS_TXD: D1.2 U7.64 | length 61.1
  Top Layer w0.25: v1(49.9,106.4) 49.88,106.4 49.84,106.36 U7.64 ; v1(61.7,153.8) 62.5,154.6 63.4,154.6 D1.2@64.5,155.7
  Bottom Layer w0.25: v1(49.9,106.4) 49.2,107.1 49.2,128.1 47.5,129.8 47.5,141.9 58.8,153.2 61.1,153.2 v1(61.7,153.8)
GND: B1.3 B1.4 BT1.2 C1.2 C2.1 C3.2 C4.1 C5.2 C6.2 C7.1 C8.2 C9.1 C10.2 C11.2 C12.1 C14.2 C15.2 C16.1 C17.2 C18.2 C19.1 C20.1 C21.2 C22.2 C23.1 C25.1 C30.2 C31.1 C32.1 C35.2 C36.2 C43.1 C46.2 C47.2 ESP1.15 P1.5 P2.1 P3.4 P4.1 P4.8 P4.10 P4.12 P4.13 P4.15 P4.16 P4.17 P4.21 P4.22 P4.23 P4.24 P4.25 P4.29 P4.30 Q1.2 Q2.2 Q3.2 Q4.2 Q5.2 R3.1 R5.1 R9.1 R22.1 R35.1 R36.1 R61.2 R66.1 R67.1 R68.1 S1.2 U1.2 U1.3 U1.8 U2.1 U3.3 U4.1 U4.3 U5.2 U6.1 U6.2 U6.3 U6.8 U7.28 U7.44 | length 49.4
  Top Layer w0.25: Q3.2@72.4,70.9 72.5,71 R66.1
  Top Layer w0.3: v1(67.4,117.6) 67.4,113.8 67.69,113.51 U7.28
  Top Layer w0.5: C32.1@46.3,87.2 46.3,77.3 55,68.6 70,68.6 Q3.2 ; U5.2 v1(84.7,143.1)
  other v1: 45.3,85.3 43.5,88.8 47.4,90.6 43.8,98.2 43,99.1 44.1,101 44,104 42.8,107.4 42.7,108.8 115.6,112.6 115.5,114.4 41.9,115.3 55.1,115.5 42,117.3 113.4,118.5 58.7,119.3 105.2,119.8 94,121.3 46.2,122.1 105,122.5 113.3,123.3 101,123.8 75.3,123.9 67.5,124 70.9,124 80.3,124 82.7,124 94.2,124 65.1,124.1 85.2,124.1 88.5,124.1 105.9,125.1 101,126.4 56.4,126.9 103.9,127.4 79.5,128.7 101.6,128.8 56.3,128.9 70.2,130.8 84.9,131.6 114,132.5 86.7,132.8 46,133 76.2,133 70.4,133.2 79.6,133.2 50.3,133.3 60.1,133.4 83,134 88.8,134 74.6,134.9 88.8,134.9 116.8,135.5 62.2,135.6 66.3,135.7 97.5,135.8 95.2,135.9 99.5,135.9 101.5,135.9 110.5,136.2 82.6,136.8 46.1,137.1 86.4,137.2 109.1,137.6 57.4,138 93.6,138 114.4,138.8 64.3,139 113.1,139.9 70.3,140.2 74.8,140.6 93.9,141.1 109.6,141.3 77.9,141.6 82.3,141.6 110.8,142.6 87.6,142.7 97.3,143.1 94.5,143.2 99.6,143.4 105.3,143.4 81.9,143.5 87.7,143.6 106.8,143.8 51,144.1 74.6,144.2 52.1,144.4 77.4,144.4 49,144.9 60.3,145.4 50,146.2 60.3,146.6 105.2,147.2 90.9,147.7 67.4,147.9 82,148.2 84.6,148.3 66.6,148.5 81.7,149.2 84.4,149.2 87.6,149.2 76.6,149.9 103.9,150 73,150.1 68.3,150.4 70.6,150.4 112.7,150.6 113.9,150.8 48.3,151.9 84.9,152.4 85.8,152.4 47.6,152.5 112.8,153 66.4,153.1 90.3,153.1 65.5,154.1 96.3,155.1 74,155.4 72.7,155.5 83.4,155.6 84.3,155.6 61.1,157 61.2,157.1 79.4,157.7 80.6,157.7 72.8,157.8 96.4,157.8 56,159.3 59,159.3 62.1,162.1 59.4,162.4 54.9,162.5 82.6,163.9 78.1,164
GPIO0_IIC_SCL: D7.1 ESP1.18 P3.2 P4.18 R40.1 U1.14 U6.14 | length 92.8
  Top Layer w0.25: P3.2 56.094,134.894 57.8,136.6 59.4,136.6 61.2,138.4 v1(61.2,138.6) 66.9,132.9 U1.14@68.4,132.9 ; v1(61.2,140.3) 64.1,143.2 v1(66.7,143.2) 67.76,144.26 U6.14 ; U1.14@68.7,132.9 69.4,132.9 70.5,131.8 v1(74.4,131.8) ; v1(78.2,128.5) 79,127.7 P4.18 ; v1(78.3,143.7) D7.1@79.4,143.7 ; v1(107.2,149.1) ESP1.18@108.6,149.1 ; ESP1.18@109,149.05 110.95,149.05 R40.1@111.5,148.5
  Bottom Layer w0.25: v1@61.2,138.8 v1(61.2,140.3) ; v1@66.825,143.325 66.85,143.3 74.245,143.3 74.32,143.375 74.88,143.375 74.955,143.3 77.9,143.3 v1(78.3,143.7) 79.1,144.5 106.2,144.5 107.8,146.1 107.8,148.5 v1(107.2,149.1) ; v1(74.4,131.8) 74.9,131.8 v1(78.2,128.5)
GPIO2_IIC_SDA: ESP1.17 P3.3 P4.19 P4.20 R39.1 U1.15 U6.15 | length 96.6
  Top Layer w0.25: P3.3 56.962,132.862 v1@57,132.9 ; v1@62,144.1 64.1,146.2 v1(66.9,146.2) 67.57,145.53 U6.15 ; v1(62.2,138.8) 66.7,134.1 U1.15@68.1,134.1 ; v1(76.4,128.4) 77.2,128.4 77.6,128 ; P4.20 77.6,128 ; P4.19 78.3,127.3 77.6,128 ; v1(106.8,147.1) 108.3,147.1 ESP1.17@108.4,147.2 ; ESP1.17 111.25,147.05 R39.1@111.3,147
  Bottom Layer w0.25: v1@57,132.9 58.6,134.5 v1(66.4,134.5) 70.3,134.5 v1(76.4,128.4) ; v1(62.2,138.8) v1(62.2,144.2) ; v1(66.9,146.2) 72.5,146.2 73.6,145.1 104.7,145.1 106.7,147.1 v1(106.8,147.1)
  other v1: 56.9,132.9
HZ/BUTY: U1.12 U7.35 | length 15.8
  Top Layer w0.25: U7.35 64.018,127.918 66.5,130.4 U1.12@68.3,130.4
K_BAT: C2.2 C3.1 C16.2 C21.1 P3.1 R2.2 U3.7 U3.8 U5.1 U5.3 | length 62.3
  Top Layer w0.3: U5.3 83.1,142.325 83.1,144.1 84.5,145.5
  Top Layer w1: P3.1@55.5,137.5 55.55,137.55 v1@55.55,145.5 ; v1(55.5,145.5) v1@55.55,145.5 ; C21.1 v1@55.55,145.5 ; U3.7@80.3,151.3 80.3,151.8 ; R2.2 80.3,151.8 ; U5.1@85.9,141.4 85.9,144.1 83.2,146.8 83.2,150.8 82.2,151.8 80.3,151.8
  Bottom Layer w1: v1(55.5,145.5) 55.5,148.314 59.186,152 82,152 v1(82.4,151.6)
K_MA: ESP1.16 R22.2 R64.2 | length 51
  Top Layer w0.25: ESP1.16 111.35,145.05 R22.2@111.4,145.1 ; R64.2 109.8,110.7 108.7,111.8 108.7,112.8 109.4,113.5 117.8,113.5 119.2,114.9 119.2,136.2 111.4,144 R22.2
K_R: ESP1.6 R33.2 | length 37.2
  Top Layer w0.25: ESP1.6 94.75,147.05 98.6,143.2 98.6,129.9 109.3,119.2 R33.2 R33.2@110.5,119.2
K_V: ESP1.5 R34.2 | length 35.6
  Top Layer w0.25: ESP1.5 96.05,149.05 100.6,144.5 100.6,132.3 109.3,123.6 R34.2@110.5,123.6
K_VR: ESP1.7 R65.2 | length 38.9
  Top Layer w0.25: ESP1.7 94.15,145.05 96.6,142.6 96.6,129.8 108.3,118.1 108.3,116.2 109.7,114.8 R65.2@110.4,114.8
KEY: D3.1 U6.10 | length 23
  Top Layer w0.25: v1(66.4,139.2) 66.42,139.18 U6.10 ; D3.1@79.7,139.3 v1(80.9,139.3)
  Bottom Layer w0.25: v1(66.4,139.2) 77.6,139.2 80.6,136.2 81.2,136.2 81.7,136.7 81.7,138.5 v1(80.9,139.3)
KEY1: P2.4 R12.1 U6.4 | length 71.3
  Top Layer w0.25: v1(57.1,142.9) 57.2,143 U6.4@58.7,143 ; U6.4 59.69,142.99 63.6,146.9 v1(65.9,146.9) ; v1(70.9,146.9) R12.1
  Bottom Layer w0.25: 50,128.8 50,128.7 ; v1(57.1,142.9) 54.2,142.9 48.5,137.2 48.5,130.2 50,128.7 ; P2.4 61.562,109.3 50.8,109.3 50,110.1 50,128.7 ; v1(65.9,146.9) v1(70.9,146.9)
KEY2: P2.5 R13.2 U6.5 | length 67.4
  Top Layer w0.25: v1(56.9,141.7) 56.92,141.72 U6.5 60.72,141.72 64.4,145.4 v1(65.9,145.4) ; v1(70.8,145.4) R13.2@71.6,145.4
  Bottom Layer w0.25: v1(56.9,141.7) 56.9,141.467 49.19,133.757 49.19,131.076 49.2,131.067 49.2,130.4 50.7,128.9 50.7,110.6 51.1,110.2 59.4,110.2 64.1,114.9 P2.5@64.8,114.9 ; v1(65.9,145.4) v1(70.8,145.4)
KEY3: P2.6 R14.1 U6.6 | length 64.8
  Top Layer w0.25: v1(56.9,140.4) 56.95,140.45 U6.6 60.35,140.45 64,144.1 v1(65.9,144.1) ; v1(70.7,144) 71.5,144 R14.1
  Bottom Layer w0.25: v1(56.9,140.4) 51.332,134.832 51.332,131.054 51.3,131.023 51.3,110.9 56.1,110.9 63.9,118.7 P2.6@64.5,118.7 ; v1(65.9,144.1) 70.6,144.1 v1(70.7,144)
KEY4: P2.3 R16.1 U6.7 | length 37.8
  Top Layer w0.25: v1(56.9,139.2) U6.7@58.2,139.2 ; U6.7 58.82,139.4 61.4,139.4 64.2,142.2 v1(66,142.2) ; v1(70.7,142.2) 71.5,142.2 R16.1@71.6,142.1
  Bottom Layer w0.25: P2.3 52.7,135 v1(56.9,139.2) ; v1(66,142.2) v1(70.7,142.2)
KEY5: P2.2 R17.1 U6.9 | length 38.8
  Top Layer w0.25: v1(66.7,137.9) 66.8,138 U6.9@68.4,138 ; U6.9 70.99,137.91 R17.1@71.8,137.1
  Bottom Layer w0.25: P2.2 52.7,116.62 53.925,117.845 53.925,133.225 58.6,137.9 v1(66.7,137.9)
LED: R7.2 U1.9 | length 35.2
  Top Layer w0.25: U1.9 68.433,121.567 70.3,119.7 94.4,119.7 R7.2@96.9,117.2
MA_IN: D14.2 K2.8 K2.9 R42.1 R43.2 R55.2 R55.3 | length 37.3
  Top Layer w0.25: R43.2 88.93,102.6 89.6,103.27 R55.2 90.376,101.924 91.3,101 R55.3 96.484,100.036 K2.8
  Top Layer w1: D14.2 99.1,97.3 K2.8@100,96.4 ; R42.1 99.49,89.51 K2.9@100.2,88.8
  Bottom Layer w1: K2.9 100.12,96.22 100.12,96.32 K2.8@100.2,96.4
MEA1: U1.4 U7.40 | length 15.9
  Top Layer w0.25: U1.4@58.8,131.5 58.9,131.6 v1(60.3,131.6) ; v1(60.3,119.3) 60.768,118.832 U7.40
  Bottom Layer w0.25: v1(60.3,119.3) v1(60.3,131.6)
MEA2: U1.5 U7.39 | length 15.3
  Top Layer w0.25: U1.5 60.98,130.32 v1(61,130.3) ; v1(61.2,119.4) 61.4,119.2 U7.39@61.4,117.7
  Bottom Layer w0.25: v1(61,130.3) 61,119.6 v1(61.2,119.4)
MEA3: U1.6 U7.38 | length 14.9
  Top Layer w0.25: U1.6@58.7,129 v1(62,129) ; U7.38 62.068,119.332 v1(62.1,119.364)
  Bottom Layer w0.25: v1(62,129) 62.1,128.9 v1(62.1,119.364)
MEA4: U1.7 U7.37 | length 14.9
  Top Layer w0.25: U1.7@58.5,127.8 v1(62.8,127.8) ; U7.37 62.8,117.492 62.8,119.2 v1(63,119.4)
  Bottom Layer w0.25: v1(62.8,127.8) 62.8,119.6 v1(63,119.4)
NetB1_1: B1.1 B1.2 D3.2 D4.2 | length 45.7
  Top Layer w0.25: D4.2 76.212,140.3 ; D3.2@76.3,139.4 76.212,139.488 76.212,140.3 ; v1(77.9,133.4) 77.9,139.8 77.4,140.3 76.212,140.3
  Bottom Layer w0.25: v1(77.9,133.4) 88.3,123 94.5,123 B1.1@99.944,117.556 ; B1.1@99.7,117.5 99.756,117.556 B1.1 B1.1@99.944,117.556 ; B1.1@100,117.5 B1.1@99.944,117.556 ; B1.2 106.183,117.505 102.596,117.505 102.545,117.556 B1.1@99.944,117.556
NetB1_6: B1.6 R7.1 | length 7.4
  Top Layer w0.25: R7.1 99.7,115.6 B1.6@103,112.3
NetC1_1: C1.1 U2.4 | length 3.3
  Top Layer w0.25: U2.4 65.341,157.559 66.6,156.3 C1.1
NetC6_1: C6.1 U2.7 Y1.2 | length 11.7
  Top Layer w0.25: U2.7 69.151,159.651 69.9,160.4 Y1.2@75.3,160.4 ; C6.1 75.4,160.3 Y1.2@75.7,160
NetC9_2: C9.2 U5.4 | length 2.5
  Top Layer w0.5: U5.4 83.75,137.25 C9.2@83.9,137.1
NetC10_1: C10.1 U2.8 Y1.1 | length 18.1
  Top Layer w0.25: U2.8 70.477,158.5 82.8,158.5 Y1.1@84.2,159.9 ; Y1.1@85,160.2 85.1,160.3 C10.1
NetC17_1: C17.1 C19.2 R20.1 R21.1 U7.58 | length 17.3
  Top Layer w0.25: C19.2 R20.1 ; v1@46.35,110.95 C17.1 ; v1(46.5,116.5) 46.5,118 R21.1 ; v1@46.6,110.7 R20.1 ; U7.58 49.6,110.26 49.47,110.26 48.855,110.875 47.545,110.875 47.325,110.655 47.325,110.025 47.3,110 R20.1
  Bottom Layer w0.25: v1(46.5,110.8) v1(46.5,116.5)
NetC18_1: C18.1 C20.2 U7.56 | length 10.1
  Top Layer w0.25: C20.2 45.2,115.6 45.2,115.45 C18.1 47.625,113.025 47.625,111.695 47.845,111.475 49.755,111.475 49.84,111.56 U7.56
NetC22_1: C22.1 C23.2 ESP1.2 R18.2 | length 7.3
  Top Layer w0.25: R18.2 87,154.4 C22.1@87.1,154.5 ; C22.1@87.5,154.7 92.25,154.7 ESP1.2
NetC24_1: C24.1 U7.55 | length 3.1
  Top Layer w0.25: C24.1 49.8,112.65 50.2,112.25 50.2,112.21 U7.55
NetC24_2: C24.2 U7.54 | length 5
  Top Layer w0.25: C24.2 50.043,114.707 50.043,113.293 50.476,112.86 U7.54
NetC25_2: C25.2 R21.2 U7.52 | length 14.2
  Top Layer w0.25: C25.2 45.9,119.5 47.3,119.5 48.2,118.6 R21.2 ; R21.2@48.2,118 50.6,118 53.5,115.1 53.5,114.5 53.16,114.16 U7.52
NetC32_2: C32.2 R23.1 U7.87 | length 14.8
  Top Layer w0.25: C32.2 R23.1 48,89.3 49.9,91.2 56.893,91.2 57.393,91.7 58,91.7 58.168,91.868 U7.87
NetC33_1: C33.1 U7.94 | length 5.3
  Top Layer w0.25: C33.1 60.1,89.3 62.718,91.918 U7.94
NetC33_2: C33.2 R27.2 U7.93 | length 9.6
  Top Layer w0.25: R27.2@58,87.5 59,87.5 ; C33.2 59,87.5 ; U7.93 62.068,92.068 61.4,91.4 60.822,91.4 59,89.578 59,87.5
NetC34_1: C34.1 P4.3 | length 4
  Top Layer w0.3: P4.3 89.5,128.4 90.4,129.3 C34.1@90.4,129.8
NetC34_2: C34.2 P4.2 | length 7.3
  Top Layer w0.3: P4.2 90.2,128 91,128.8 91.7,128.8 91.8,128.9 91.8,130.9 91.3,131.4 C34.2
NetC37_1: C37.1 P4.5 | length 5.9
  Top Layer w0.3: P4.5 88.1,128.5 87.8,128.8 87.8,130.4 C37.1@88.9,131.5
NetC37_2: C37.2 P4.4 | length 3.7
  Top Layer w0.3: P4.4 88.8,129.6 C37.2@89,129.8
NetC38_1: C38.1 R30.1 U7.98 | length 8.9
  Top Layer w0.25: R30.1 63.3,90.2 64.1,91 65.2,91 65.3,90.9 ; U7.98 65.3,93.342 65.3,90.9 ; C38.1@67.6,89.3 66,90.9 65.3,90.9
NetC38_2: C38.2 R32.2 R32.3 | length 7.2
  Top Layer w0.25: C38.2 68.4,87.05 69.156,87.05 R32.2 70.176,85.924 R32.3@71.2,84.9
NetC39_1: C39.1 U7.14 | length 10.1
  Top Layer w0.25: U7.14 73.09,104.41 73.6,103.9 78.3,103.9 C39.1@78.9,104.5
NetC40_1: C40.1 C41.2 R31.2 R37.1 R38.1 U7.1 | length 18
  Top Layer w0.25: U7.1 70.4,94.778 70.4,91.5 ; R31.2@70.4,90.2 70.4,91.5 ; C40.1@74.9,83.4 74.9,88.1 74.9,90.1 74.7,90.3 73.7,90.3 72.5,91.5 70.4,91.5
NetC40_2: C40.2 C44.2 C45.2 D10.1 R37.2 U7.6 | length 30.2
  Top Layer w0.25: U7.6 73.86,99.21 74.295,98.775 75.355,98.775 75.575,98.555 75.575,97.925 75.6,97.9 C45.2 ; R37.2 78.1,84 79.8,84 D10.1@80.6,84.8 ; C44.2 76.9,94.1 77.5,94.7 ; C45.2@76.5,97.9 77.5,96.9 77.5,94.7 ; C40.2 78.25,85.65 v1(78.3,85.7) ; v1(78.3,94.7) 77.5,94.7
  Bottom Layer w0.25: v1(78.3,85.7) v1(78.3,94.7)
NetC41_1: C41.1 D11.3 R38.2 R52.1 | length 8.9
  Top Layer w0.25: R38.2 v1(77.25,89.45) 78.6,88.1 80.1,88.1 D11.3@80.4,88.4 ; R52.1@76.5,92.5 v1(77.3,92.5)
  Bottom Layer w0.25: v1(77.25,89.45) 77.25,92.45 v1(77.3,92.5)
NetC42_1: C42.1 U7.27 | length 8.8
  Top Layer w0.25: U7.27 70.86,112.86 72.7,114.7 72.7,116.6 74.3,118.2 C42.1
NetC43_2: C43.2 P4.14 R41.2 | length 6.6
  Top Layer w0.25: C43.2@77.7,129.9 79.5,129.9 81,128.4 81.3,128.4 81.8,127.9 P4.14
NetC44_1: C44.1 R52.2 R59.1 | length 3.6
  Top Layer w0.25: R52.2 C44.1 R59.1 R59.1@74.8,96.1
NetC45_1: C45.1 R59.2 U7.4 | length 8.1
  Top Layer w0.25: U7.4 74.69,97.91 C45.1 75.7,96.9 75.7,96.7 R59.2
NetC46_1: C46.1 P4.27 | length 4.6
  Top Layer w0.3: P4.27 72.7,128 74.1,129.4 C46.1@74.1,130.2
NetC47_1: C47.1 P4.28 | length 3.9
  Top Layer w0.3: C47.1@71.9,130.1 72,130 P4.28
NetD2_2: D2.2 U2.2 | length 2.9
  Top Layer w0.25: D2.2@62,156 62.801,156.801 U2.2
NetD5_2: D5.2 R8.1 | length 5.3
  Top Layer w0.25: R8.1 73.9,138.8 74.8,137.9 74.8,136.1 D5.2@76,134.9
NetD6_2: D6.2 R10.1 | length 4.4
  Top Layer w0.25: R10.1 73.4,140.33 74.275,139.455 74.275,139.325 D6.2@76.3,137.3
NetD7_2: D7.2 D8.2 S1.1 | length 45.8
  Top Layer w0.25: D8.2@76.1,145.8 76.212,145.688 D7.2 ; D8.2 76.512,146.2 v1(77.4,146.2)
  Bottom Layer w0.25: v1(77.4,146.2) 102.6,146.2 108.3,151.9 114.7,151.9 S1.1@116.6,150
NetD10_2: D10.3 D11.1 U7.3 | length 23.1
  Top Layer w0.25: U7.3 70.64,97.26 71.5,96.4 71.5,93.7 73.9,91.3 77.4,91.3 78.7,90 80.4,90 D11.1 ; D10.3 83.05,87.35 D11.1@83.2,87.5
NetD12_1: D12.1 R60.1 U7.13 | length 17
  Top Layer w0.25: U7.13 72.74,103.76 73.1,103.4 83.2,103.4
  Top Layer w0.5: R60.1 83.2,103.4 83.2,102.5 D12.1@83.7,102
NetD12_2: D12.2 D13.1 | length 6.7
  Top Layer w0.25: D12.2@83.3,100.2 D12.2@83.3,100.4
  Top Layer w0.5: D13.1 79,102.3 82,102.3 82.6,101.7 82.6,100.9 83.2,100.3 D12.2@83.7,100.3
NetD14_1: D14.1 D15.1 | length 3.3
  Top Layer w1: D15.1 80.5,97.3 D14.1 D14.1@83.1,97.3
NetD14_3: D14.3 D15.2 | length 3
  Top Layer w1: D15.2 82.9,92.3 D14.3@83,92.2
NetESP1_3: ESP1.3 R19.2 | length 4.1
  Top Layer w0.25: R19.2@89.3,151 89.9,151 91.95,153.05 ESP1.3
NetK1_15: K1.15 Q2.3 | length 30.6
  Top Layer w0.5: v1(112.2,102) 113.04,102 K1.15 ; Q2.3@116.8,124.6 v1(118.2,124.6)
  Bottom Layer w0.5: v1(112.2,102) 112.2,118.6 v1(118.2,124.6)
NetK1_16: K1.16 Q1.3 | length 25.5
  Top Layer w0.5: v1(113.2,103.9) 113.8,103.9 K1.16@117.9,99.8 ; Q1.3 v1(117.8,120)
  Bottom Layer w0.5: v1(113.2,103.9) 113.2,115.4 v1(117.8,120)
NetK2_15: K2.15 Q5.3 | length 30.2
  Top Layer w0.5: Q5.3 v1(117.9,115.7)
  Bottom Layer w0.5: K2.15@115.3,88.8 114.06,90.04 114.06,108.621 117.9,112.461 v1(117.9,115.7)
NetK2_16: K2.16 Q4.3 | length 25.5
  Top Layer w0.5: Q4.3 118,111.5 119,110.5 v1(119,108.9)
  Bottom Layer w0.5: K2.16@117.8,88.7 119.7,90.6 119.7,108.2 v1(119,108.9)
NetLS1_1: LS1.1 Q3.3 | length 8
  Top Layer w0.5: Q3.3 73.85,68.35 78.1,72.6 LS1.1@78.1,73.9
NetP4_26: P4.26 R61.1 | length 5.4
  Top Layer w0.3: P4.26 73.4,127.8 74.3,128.7 75.1,128.7 R61.1@76.3,129.9
NetQ1_1: Q1.1 R33.1 R35.2 | length 3.9
  Top Layer w0.25: R33.1 R35.2 Q1.1@114.3,120.8
NetQ2_1: Q2.1 R34.1 R36.2 | length 3.8
  Top Layer w0.25: R34.1 R36.2 114.1,125.2 Q2.1@114.2,125.3
NetQ3_1: Q3.1 R62.1 R66.2 | length 3.5
  Top Layer w0.25: R62.1 R66.2 74.1,70.9 Q3.1@74.2,70.8
NetQ4_1: Q4.1 R64.1 R67.2 | length 4.1
  Top Layer w0.25: R64.1 R67.2 114.4,112.3 Q4.1@114.5,112.2
NetQ5_1: Q5.1 R65.1 R68.2 | length 3.9
  Top Layer w0.25: R65.1 R68.2 Q5.1@114.3,116.5
NetR4_2: R4.2 R6.2 U3.2 | length 8.4
  Top Layer w0.25: R4.2@71.7,152.4 72.4,152.4 73.692,151.108 U3.2 76.208,151.108 76.8,151.7 R6.2@76.8,154.2
NetR5_2: R5.2 U4.2 | length 3.4
  Top Layer w0.25: U4.2 57.235,160.635 R5.2@57.5,160.9
NetR8_2: R8.2 R9.2 R10.2 U3.4 | length 14.8
  Top Layer w0.25: R10.2@71.7,140.6 R10.2 ; R8.2 71.8,139.9 70,141.7 70,147.2 R9.2 71.9,148.7 U3.4@74.7,148.7
NetR11_1: R11.1 U7.61 Y2.2 | length 10.1
  Top Layer w0.25: R11.1 45.5,105.6 48.21,108.31 U7.61
NetR11_2: R11.2 U7.62 Y2.1 | length 21.3
  Top Layer w0.25: R11.2 42.7,100.8 Y2.1@46.3,97.2 ; Y2.1@46.7,97.6 49.1,100 49.1,106.625 50.135,107.66 U7.62
NetR20_2: R20.2 U7.59 | length 3.6
  Top Layer w0.25: R20.2 48.9,110 49.29,109.61 U7.59
NetR24_1: R24.1 R25.1 | length 2.3
  Top Layer w0.25: R24.1@53.2,85.3 53.87,85.97 R25.1
NetR25_2: R25.2 R25.3 R26.2 U7.89 | length 11.7
  Top Layer w0.25: R25.3@50.7,88.1 51.7,89.1 55.5,89.1 57.2,90.8 58.1,90.8 58.593,91.293 ; 58.593,91.293 59.4,92.1 ; 59.4,92.1 59.468,92.168 U7.89 U7.89@59.5,93.328
NetR26_1: R26.1 U7.90 | length 8.2
  Top Layer w0.25: R26.1 56.7,88.4 56.7,89.593 57.407,90.3 58.293,90.3 ; 58.3,90.3 58.308,90.3 60.118,92.11 U7.90
NetR27_1: R27.1 U7.91 | length 5.8
  Top Layer w0.25: R27.1@57.9,89.1 R27.1@58,89.2 ; R27.1@57.9,89.2 57.915,89.2 60.768,92.053 U7.91 ; R27.1@58.1,89.1 R27.1@58.1,89.4
NetR28_1: R28.1 R29.2 U7.96 | length 13
  Top Layer w0.25: R29.2 61.7,86.5 62.1,86.1 64.4,86.1 64.9,86.6 R28.1 ; v1(63.3,91.3) 64.018,92.018 U7.96
  Bottom Layer w0.25: v1(63.3,86.1) v1(63.3,91.3)
NetR29_1: R29.1 R30.2 | length 2.3
  Top Layer w0.25: R29.1 62.4,88.4 R30.2
NetR31_1: R31.1 R32.1 | length 2.1
  Top Layer w0.25: R32.1 R31.1@72.024,90.124
NetR43_1: R43.1 U7.8 | length 20.4
  Top Layer w0.25: U7.8 73.267,100.51 74.077,99.7 77.2,99.7 77.8,99.1 86.3,99.1 R43.1@88.2,101
NetR44_1: R44.1 U7.9 | length 5.6
  Top Layer w0.25: U7.9 74.34,101.16 R44.1
NetR45_1: R45.1 U7.11 | length 5.4
  Top Layer w0.25: U7.11 74.56,102.46 R45.1@74.6,102.5
NetR46_1: R46.1 U7.15 | length 5.5
  Top Layer w0.25: U7.15 73.96,105.06 74,105.1 R46.1
NetR47_1: R47.1 U7.17 | length 5.6
  Top Layer w0.25: U7.17 73.66,106.36 74,106.7 R47.1
NetR47_2: R47.2 R58.2 R58.3 | length 6.2
  Top Layer w0.25: R47.2 77.6,106.7 79.5,108.6 R58.2@81.7,108.6
NetR48_1: R48.1 U7.18 | length 6
  Top Layer w0.25: U7.18 72.71,107.01 74,108.3 R48.1
NetR49_1: R49.1 U7.20 | length 6.1
  Top Layer w0.25: U7.20 72.41,108.31 74,109.9 R49.1
NetR50_1: R50.1 U7.22 | length 6.3
  Top Layer w0.25: U7.22 72.11,109.61 74,111.5 R50.1
NetR50_2: R50.2 R56.1 | length 2.3
  Top Layer w0.25: R56.1 R50.2
NetR51_1: R51.1 U7.24 | length 7.8
  Top Layer w0.25: U7.24 71.91,110.91 73.4,112.4 73.4,113.7 74.4,114.7 R51.1
NetR51_2: R51.2 R57.1 | length 2.3
  Top Layer w0.25: R57.1 75.6,115.4 R51.2
NetR53_1: R53.1 U7.26 | length 18.3
  Top Layer w0.25: U7.26 71.49,112.21 v1(71.6,112.1) ; v1(86,112) 87.3,112 R53.1@87.4,111.9
  Bottom Layer w0.25: v1(71.6,112.1) 85.9,112.1 v1(86,112)
PWR: D5.1 ESP1.19 | length 49.5
  Top Layer w0.25: D5.1 86.095,134.905 87.9,133.1 v1(93.2,133.1) ; ESP1.19@109,151.2 109.1,151.1 v1(110.2,151.1)
  Bottom Layer w0.25: v1(93.2,133.1) 92.1,134.2 92.1,141.1 93.1,142.1 106.5,142.1 110.2,145.8 v1(110.2,151.1)
RANGE: U1.11 U7.32 | length 13.1
  Top Layer w0.25: U7.32 65.968,127.468 67.6,129.1 U1.11@68.3,129.1
RXD0: D1.1 D2.1 ESP1.21 R1.1 | length 56.9
  Top Layer w0.25: R1.1@61.9,150.1 62.005,150.205 D2.1 64.331,152.531 D1.1@64.5,152.7 ; 63.2,152.6 v1(63.2,153.7) ; ESP1.21 v1@110.45,155.05
  Bottom Layer w0.25: v1(63.2,153.7) 65.8,156.3 109.3,156.3 v1(110.5,155.1)
SELECT: U1.10 U7.31 | length 11.5
  Top Layer w0.25: U7.31 66.618,126.918 67.5,127.8 U1.10@68.2,127.8
SMV: K1.8 R60.2 | length 16.5
  Top Layer w0.5: R60.2 97.6,104.7 K1.8@100.2,107.3
TENM: K1.9 R53.2 R54.1 | length 18.6
  Top Layer w0.25: R53.2 R54.1 v1(91.5,110.6) ; v1(95.8,103.2) 99.2,99.8 K1.9@100.2,99.8
  Bottom Layer w0.25: v1(91.5,110.6) 91.5,107.5 v1(95.8,103.2)
TXD0: ESP1.22 U2.3 | length 51
  Top Layer w0.25: v1(64,156.9) 64.071,157.129 U2.3 ; ESP1.22@108.6,157.1 110.6,156.9 v1(110.8,157.2)
  Bottom Layer w0.25: v1(64,156.9) 110.6,156.9 v1(110.8,157.2)
UP_K: D4.1 D8.1 R6.1 U3.5 U3.6 | length 16.4
  Top Layer w0.25: R6.1@78.8,154.1 77.9,153.2 77.9,150.5 78.562,149.838 U3.6 U3.5@79.9,148.6 ; D4.1@79.7,141.3 79.9,141.3 80.9,142.3 80.9,144.474 D8.1 79.9,146.336 U3.5@79.9,148.6 ; U3.5@79.9,148.7 U3.5@79.9,148.6 ; U3.5@80,148.5 U3.5@79.9,148.6
USB+: P1.3 U2.5 | length 25.7
  Top Layer w0.25: P1.3 46.7,154.1 46.9,153.9 v1(47.9,153.9) ; v1(66.6,160.2) 66.611,160.189 U2.5
  Bottom Layer w0.25: v1(47.9,153.9) 54.2,160.2 v1(66.6,160.2)
USB-: P1.2 U2.6 | length 27.7
  Top Layer w0.25: P1.2 v1@47.25,154.75 ; v1(67.9,161) 67.9,158.7 U2.6@68,158.6
  Bottom Layer w0.25: v1@47.25,154.75 53.5,161 v1(67.9,161)
  other v1: 47.2,154.7
V_BAT: BT1.1 C7.2 C8.1 R4.1 U3.1 U4.5 | length 25.4
  Top Layer w1: 53.8,150.6 56.6,150.6 58.9,148.3 64.4,148.3 68,151.9 68,153.4 68.7,154.1 72.8,154.1 U3.1@74.3,152.6
VCC: B1.5 C4.2 C5.1 C14.1 C15.1 C26.1 C27.2 C35.1 C36.1 ESP1.8 K1.1 K1.2 K2.1 K2.2 LS1.2 P4.7 P4.9 P4.11 R1.2 R12.2 R13.1 R14.2 R15.2 R16.2 R17.2 R19.1 R23.2 R39.2 R40.2 R41.1 U1.1 U1.16 U5.5 U6.16 U7.48 | length 386.8
  Top Layer w0.25: R1.2 64.4,150.2 v1(64.7,150.5) ; v1(68.2,149.1) 69.3,149.1 C14.1@69.4,149 ; C15.1@71.6,135.5 71.7,135.5 R17.2 ; R15.2 89.9,156.1 93.7,156.1 94.3,155.5 v1(94.3,152.3) ; R19.1@89.4,149.2 89.3,149.1 v1(89.3,148.1) 90.8,146.6 90.8,143 ; R40.2 114.1,147.4 v1(114.1,146.9) R39.2@113.1,146.9
  Top Layer w0.3: C27.2@54.7,120.7 54.7,120.6 54.7,120 55.568,119.132 U7.48 ; R41.1 80.5,131.5 81.3,130.7 C35.1@81.3,130.3 ; C36.1@83.3,129.9 83.9,129.3 P4.11 ; C36.1@83.5,130 85.3,130 86.7,128.6 P4.7 ; C36.1@83.8,129.9 85.3,128.4 P4.9
  Top Layer w0.5: v1(45.3,88.8) 45.7,89.2 R23.2 ; v1(47.4,85.4) 47.4,77.4 55.4,69.4 68.7,69.4 71.4,72.1 71.4,76.6 72.9,78.1 81.22,78.1 LS1.2@85.41,73.91 ; C26.1@52.8,122.9 52.8,122.5 54.7,120.6 C27.2 ; C26.1@53.2,122.8 v1(55.1,124.7) ; U1.1 59.5,135.4 v1(60.8,136.7) ; U1.16 70.2,135.4 ; U6.16@69.3,146.8 v1(69.3,147.7) 69.3,148.8 C14.1 ; v1(70.2,136.7) 70.2,135.4 ; C15.1@71.9,135.3 71.8,135.4 70.2,135.4 ; R16.2 R14.2 R13.1 73.4,146 ; 73.4,142.7 v1(74.6,142.7) ; R12.2 73.4,146 ; v1(74.4,146.1) 74.3,146 73.4,146 ; C35.1@81.3,130.3 81.6,130 v1(82.6,130) C36.1@83.4,130 ; LS1.2@85.4,73.9 LS1.2@85.41,73.91 ; LS1.2 LS1.2@85.41,73.91 ; K1.2@115.3,107.4 118.2,107.4 119.3,106.3 119.3,96.4 ; K2.2 K2.1 119.3,96.4 ; LS1.2@85.41,73.91 98.1,86.6 118.4,86.6 119.3,87.5 119.3,96.4
  Top Layer w1: U5.5 87.6,139.525 ; v1(87.6,138.5) 87.6,139.525 ; C4.2 89.5,143 90.8,143 92.2,143 92.2,142.1 89.625,139.525 87.6,139.525 ; C5.1 v1(93.5,139.8)
  Bottom Layer w0.25: v1(64.7,150.5) 66.8,150.5 v1(68.2,149.1) ; v1(89.3,148.1) 90.1,148.1 v1(94.3,152.3) ; B1.5 103,139.5 ; 109.9,139.8 114.1,144 v1(114.1,146.9)
  Bottom Layer w0.5: v1(45.3,88.8) 45.3,87.5 v1(47.4,85.4) ; v1(55.1,124.7) 55.1,132.3 59.5,136.7 78.1,136.7 79.3,135.5 86.3,135.5 87.6,136.8 v1(87.6,138.5) 82.9,138.5 78.7,142.7 v1(74.6,142.7) ; v1(69.3,147.7) 72.8,147.7 v1(74.4,146.1) ; v1(82.6,130) 82.6,131.8 85.2,134.4 86.3,134.4 88.4,136.5 v1(88.4,139.4)
  Bottom Layer w1: v1(93.5,139.8) 109.9,139.8 119.5,130.2 119.5,111.5 117.8,109.8 K1.1@117.8,107.3
VM: K1.13 R46.2 R48.2 R49.2 R56.2 R57.2 R58.1 | length 62.1
  Top Layer w0.25: R48.2 R49.2@76.3,109.8
  Top Layer w0.5: R46.2 77.1,105.1 78,106 80.8,106 81.7,106.9 82.8,106.9 83.3,107.4 83.3,109.4 ; R56.2 77.8,113.1 ; R49.2@76.4,110.1 76.5,110.2 78.6,110.2 ; R57.2@76.4,116.3 77.4,116.3 77.8,115.9 77.8,111 78.6,110.2 ; K1.13@110.4,99.6 107.9,102.1 107.9,107.4 105.9,109.4 83.3,109.4 ; 78.6,110.2 82.5,110.2 83.3,109.4
VR_IN: K1.4 K2.6 K2.11 R54.2 | length 39.9
  Top Layer w0.25: R54.2 96.5,111.7 97.6,110.6 107.1,110.6 K1.4@110.4,107.3
  Bottom Layer w1: K2.11 K2.6 ; K2.6@105.2,96.5 K2.6 ; K1.4@110.3,107.3 108,105 108,99.2 105.8,97 K2.6
pads on no net: D10.2 D11.2 D12.3 D13.3 ESP1.9 ESP1.10 ESP1.11 ESP1.12 ESP1.13 ESP1.14 J1.1 J2.1 J3.1 J4.1 J7.1 K1.6 P1.4 P2.0 P3.5 P3.6 P4.6 S1.0 U1.13 U2.9 U2.10 U2.11 U2.12 U2.13 U2.14 U2.15 U4.0 U4.6 U6.12 U6.13 U7.10 U7.16 U7.29 U7.30 U7.33 U7.34 U7.36 U7.41 U7.42 U7.43 U7.45 U7.47 U7.49 U7.50 U7.51 U7.53 U7.57 U7.60 U7.63 U7.65 U7.66 U7.67 U7.68 U7.69 U7.70 U7.71 U7.72 U7.73 U7.74 U7.75 U7.76 U7.77 U7.78 U7.79 U7.80 U7.81 U7.82 U7.83 U7.86 U7.88 U7.92 U7.97
copper on no net:
  other v2: 44.8,68.041 116.8,68.041 43.276,68.676 46.324,68.676 115.276,68.676 118.324,68.676 42.641,70.2 46.959,70.2 114.641,70.2 118.959,70.2 43.276,71.724 46.324,71.724 115.276,71.724 118.324,71.724 44.8,72.359 116.8,72.359 84.6,114.141 83.076,114.776 86.124,114.776 82.441,116.3 86.759,116.3 83.076,117.824 86.124,117.824 84.6,118.459 44.8,160.041 116.8,160.041 43.276,160.676 46.324,160.676 115.276,160.676 118.324,160.676 42.641,162.2 46.959,162.2 114.641,162.2 118.959,162.2 43.276,163.724 46.324,163.724 115.276,163.724 118.324,163.724 44.8,164.359 116.8,164.359
  other v3: 54.5,154.3 56.6,154.3 58.7,154.3 54.5,155.6 56.6,155.6 58.7,155.6

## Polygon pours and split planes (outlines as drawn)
GND on Bottom Layer "Bottom Layer-No Net" (hatched 90Degree grid 0.508 track 0.203, remove dead copper): 47.4,83.5 41.4,83.5 41.4,165.6 41.3,165.7 120.2,165.7 120.2,110 111.3,110 111.3,112.1 99.6,112.1 98.6,113.1 92.2,119.5 70.6,119.5 65.9,114.8 65.9,112.9 55.4,102.4 55.4,97.1 47.4,89.1 47.4,83.5
B- on Bottom Layer "Bottom Layer-No Net" (hatched 90Degree grid 0.508 track 0.203, pour order 1000): 58.6,83.5 50.6,83.5 49.4,84.7 49.4,87.5 57,95.1 57,100.8 59.1,102.9 66.9,110.7 66.9,114.1 68.6,115.8 81.6,115.8 93.8,115.8 98.2,111.4 98.2,83.5
GND on Top Layer "Bottom Layer-No Net" (hatched 90Degree grid 0.508 track 0.203, remove dead copper): 47.4,83.5 41.4,83.5 41.4,165.6 41.3,165.7 120.2,165.7 120.2,110 111.3,110 111.3,112.1 99.6,112.1 98.6,113.1 92.2,119.5 70.6,119.5 65.9,114.8 65.9,112.9 55.4,102.4 55.4,97.1 47.4,89.1 47.4,83.5

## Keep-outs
Keep-Out Layer:
  lines w0.2: 40.8,66.2 40.8,166.2 120.8,166.2 120.8,66.2 40.8,66.2
  lines w0.3: 70.9,120.4 90.7,120.4 90.7,121.7 70.9,121.7 70.9,120.4

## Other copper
Top Layer:
  rectangle net B-: 66.4,95.1 67.6,112.8
  rectangle: 53.7,153.8 59.8,156.1
  pour cut-out: 92.6,157.9 86.9,163.6 86.9,166.2 114.4,166.2 114.4,163.8 108.5,157.9
  region net V_BAT: 54.4,153.1 51.1,149.8 49.2,149.8 46.5,147.1 46.5,145.9 48,145.9 50.2,148.1 52.2,148.1 53.2,149.1 53.2,149.6 55,151.4 55,153.1
  region net 5V: 45.7,155.6 48.6,158.5 50.4,158.5 51.8,159.9 51.8,161.1 52.8,161.1 52.8,160.2 55,158 55,156.9 54.8,156.7 49.5,156.7 48.1,155.3 45.7,155.3
Bottom Layer:
  rectangle net B-: 67.2,75.8 70.1,83.9
  rectangle: 53.7,153.8 59.8,156.1
  pour cut-out: 92.6,157.9 86.9,163.6 86.9,166.2 114.4,166.2 114.4,163.8 108.5,157.9

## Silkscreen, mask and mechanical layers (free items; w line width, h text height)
Top Overlay:
  drawing of 1167 lines, arcs and shapes, not listed
  text "Wi" at 109.9,165 h3 r270
  text "Fi" at 110,160.9 h3 r270
  text "V2.1.0" at 111.4,130.2 h3
Bottom Overlay:
  drawing of 4164 lines, arcs and shapes, not listed
  text "Fi" at 99.403,157.773 h3
  text "Wi" at 103.503,157.673 h3
  text "update" at 107.4,147.3 h2.5
  text "run" at 112.3,147.3 h2.5
  text "+" at 50.1,146.6 h2
  text "VCC" at 54.7,138.1 h2
  text "I2C" at 44.6,135.1 h2.5 r90
  text "SCL" at 54.7,135 h2
  text "SDA" at 54.8,131.7 h2
  text "GND" at 54.8,128.5 h2
  text "开源  开放  自由" at 85.1,93.8 h3
  text "www.iot7.cn" at 85.1,90.7 h2.5

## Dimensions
40.8,66.2 to 40.8,166.2 on Mechanical 1
40.8,66.2 to 120.8,66.2 on Mechanical 1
